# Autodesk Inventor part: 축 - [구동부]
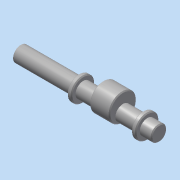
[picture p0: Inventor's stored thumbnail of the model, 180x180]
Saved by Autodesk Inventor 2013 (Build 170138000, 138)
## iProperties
Company: 한국ATC센터
Created: 2014-08
Part Number: 축 - [구동부]
Document SubType Name: Modeling
Designer: KYOUNG IL JANG
Density: 7.86 g/cm^3
Material: 강철, 연강
Mass: 375.453 g
Surface Area: 117.379 cm^2
Volume: 47.7676 cm^3
Author: KYOUNG IL JANG
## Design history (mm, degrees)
sketch "스케치1"
  geometry: L1 (-76.5, 0)-(76.5, 0); L2 (-76.5, 0)-(-76.5, 8.5); L3 (-76.5, 8.5)-(-12.5, 8.5); L4 (-12.5, 8.5)-(-12.5, 13); L5 (-12.5, 13)-(-7.5, 13); L6 (-7.5, 13)-(-7.5, 8.5); L7 (-7.5, 8.5)-(58.5, 8.5); L8 (58.5, 8.5)-(58.5, 13); L9 (58.5, 13)-(63.5, 13); L10 (63.5, 13)-(63.5, 8.5); L11 (63.5, 8.5)-(76.5, 8.5); L12 (76.5, 8.5)-(76.5, 0); 2 further points
  constraints: 24 end point, 5 parallel, 1 coincident, 1 horizontal, 1 midpoint, 1 perpendicular
  dimensions: "d0" = 153 distance of L1.start L1.end (derived); "d2" = 17 diameter of L3 L1; "d3" = 26 diameter of L5 L1; "d4" = 17 diameter of L7 L1; "d5" = 26 diameter of L9 L1; "d6" = 17 diameter of L11 L1; "d7" = 5 distance of L8.end L9.end; "d8" = 5 distance of L4.end L5.end; "d10" = 64 distance of L2.end L3.end; "d11" = 13 distance of L10.end L11.end; "d35" = 66 distance between parallel lines of L8 L6
revolve "회전1" sketch "스케치1" stored, may be unused: angle "d12" = 90 deg
node "작업 평면1"
node "작업 평면2"
node "작업 평면4"
sketch "스케치6"
  geometry: C1 r 15 at (-5, -6); 1 further point
  constraints: 1 centre point, 1 horizontal alignment
  dimensions: "d31" = 30 diameter of C1; "d32" = 5 distance of C1.centre point (0, -6)
extrude "돌출4" join sketch "스케치6" stored distance "d33" = 22; taper "d34" = 0 deg
node "작업 평면3"
sketch "스케치5"
  geometry: L1 (32, 8.5)-(32, -8.5) reference; L2 (32, -2.5)-(14.5, -2.5); L3 (14.5, 2.5)-(32, 2.5); A1 r 2.5 centre (14.5, 0) between (14.5, 2.5) and (14.5, -2.5); 2 further points
  constraints: 4 end point, 2 point on circle, 2 point on line, 2 tangent, 1 centre point, 1 midpoint, 1 parallel, 1 perpendicular
  dimensions: "d23" = 5 distance between parallel lines of L3 L2; "d36" = 20 dimension on A1 L1
extrude "돌출3" cut sketch "스케치5" distance "d25" = 3; taper "d26" = 0 deg
chamfer "모따기1" distance "d27" = 1; stored, may be unused: second distance "d28" = 2, angle "d29" = 45 deg
node "솔리드1"
other parameters: "d13" = 9.5, "d18" = 9.5
